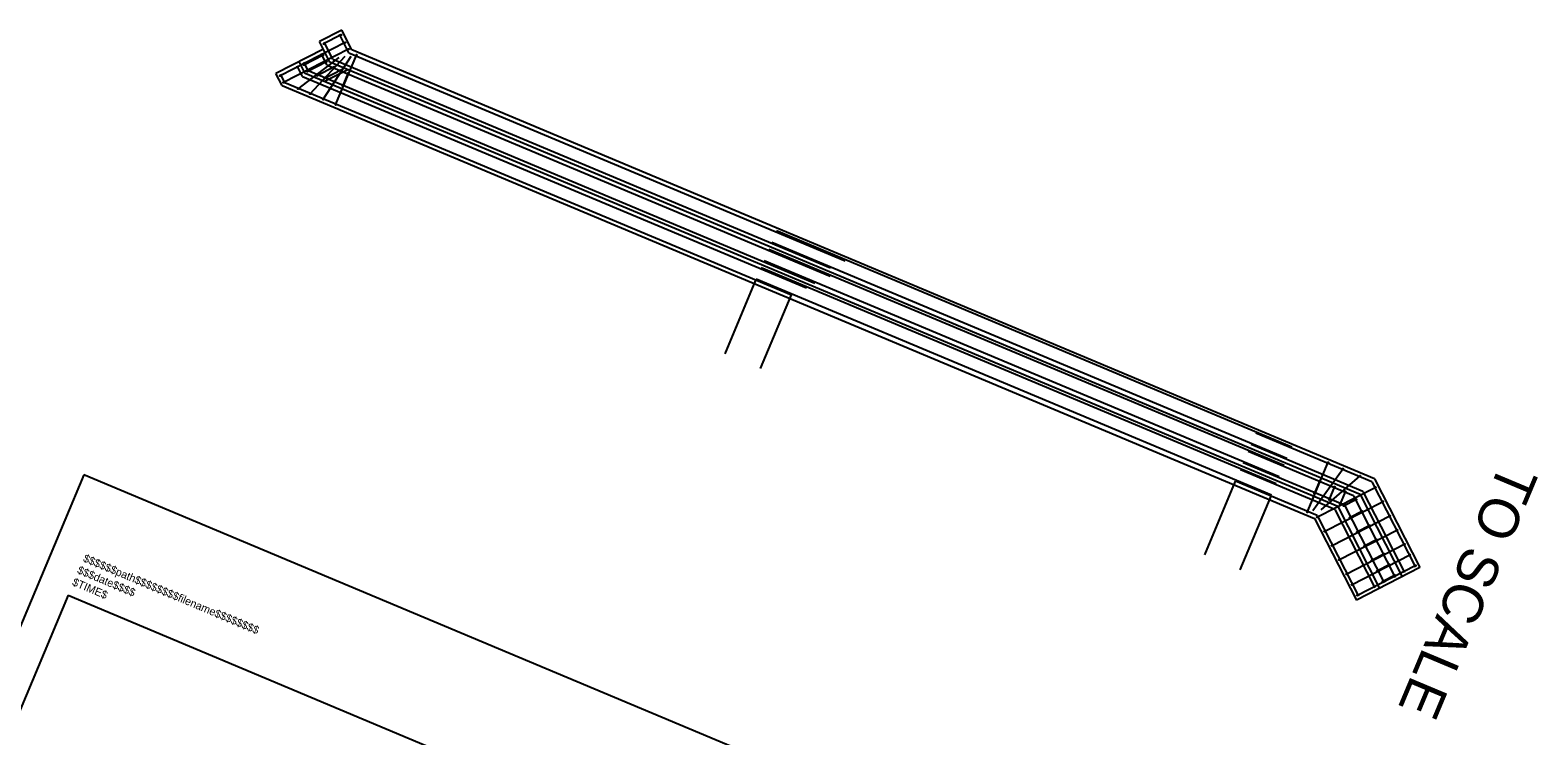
# Model space of a CAD drawing. Extents: x 1968564 to 1968711, y 796599 to 796794.
# Drawn here: x 1968616.2 to 1968710.6, y 796749.4 to 796793.6 of the extents above; entities that cross this region are included whole.
import ezdxf

# ---------------------------------------------------------------- set-up
doc = ezdxf.new("R2010")
doc.units = 0
for name, color, linetype in [('BR_BORDER LINES', 7, 'Continuous'), ('BR_CONCRETE', 7, 'Continuous'), ('BR_REBAR', 7, 'Continuous'), ('Level 31', 7, 'Continuous'), ('RD_SHT_ID', 7, 'Continuous')]:
    doc.layers.add(name, color=color, linetype=linetype)

msp = doc.modelspace()

# ---------------------------------------------------------------- linework, layer by layer
at = {"layer": 'BR_BORDER LINES'}
for q in [(1968566.464, 796634.028), (1968696.012, 796725.723)]:
    msp.add_line((1968618.549, 796758.212), q, dxfattribs=at)
at = {"layer": 'BR_CONCRETE'}
for p, q in [((1968635.689, 796793.605), (1968634.291, 796792.889)), ((1968636.316, 796792.381), (1968635.689, 796793.605)), ((1968634.538, 796792.407), (1968631.57, 796790.887)), ((1968634.952, 796791.597), (1968634.291, 796792.889)), ((1968700.385, 796765.509), (1968636.316, 796792.381)), ((1968633.405, 796790.89), (1968633.026, 796791.632)), ((1968636.067, 796791.13), (1968634.612, 796790.385)), ((1968699.481, 796764.533), (1968634.952, 796791.597)), ((1968631.95, 796790.145), (1968631.57, 796790.887)), ((1968631.95, 796790.145), (1968696.629, 796763.018)), ((1968698.084, 796763.763), (1968633.405, 796790.89)), ((1968700.385, 796765.509), (1968703.236, 796759.941)), ((1968698.084, 796763.763), (1968700.705, 796758.645)), ((1968699.481, 796764.533), (1968702.124, 796759.371)), ((1968696.629, 796763.018), (1968699.25, 796757.9)), ((1968703.236, 796759.941), (1968699.25, 796757.9))]:
    msp.add_line(p, q, dxfattribs=at)
at = {"layer": 'BR_REBAR'}
for p, q in [((1968635.655, 796793.306), (1968634.553, 796792.742)), ((1968636.143, 796792.194), (1968635.552, 796793.347)), ((1968635.902, 796792.824), (1968631.833, 796790.74)), ((1968636.113, 796792.411), (1968632.044, 796790.328)), ((1968633.318, 796791.427), (1968634.534, 796792.049)), ((1968634.779, 796791.41), (1968634.401, 796792.149)), ((1968634.516, 796789.25), (1968636.274, 796791.984)), ((1968635.126, 796791.784), (1968634.58, 796792.85)), ((1968635.305, 796788.919), (1968636.626, 796792.07)), ((1968636.143, 796792.194), (1968667.224, 796779.158)), ((1968633.232, 796790.703), (1968632.888, 796791.375)), ((1968632.938, 796789.915), (1968635.525, 796791.882)), ((1968633.579, 796791.078), (1968633.315, 796791.593)), ((1968633.529, 796791.014), (1968634.745, 796791.637)), ((1968633.579, 796791.078), (1968665.321, 796777.764)), ((1968633.696, 796789.595), (1968635.902, 796791.982)), ((1968635.226, 796791.309), (1968634.144, 796790.754)), ((1968635.68, 796791.119), (1968634.597, 796790.564)), ((1968634.779, 796791.41), (1968666.289, 796778.194)), ((1968635.126, 796791.784), (1968666.298, 796778.71)), ((1968632.124, 796790.332), (1968631.86, 796790.848)), ((1968632.124, 796790.332), (1968663.866, 796777.019)), ((1968633.232, 796790.703), (1968664.813, 796777.458)), ((1968636.099, 796790.935), (1968635.745, 796790.09)), ((1968695.202, 796767.49), (1968662.926, 796781.027)), ((1968694.719, 796766.338), (1968662.442, 796779.875)), ((1968694.904, 796766.779), (1968662.628, 796780.316)), ((1968694.42, 796765.627), (1968662.144, 796779.164)), ((1968659.703, 796773.343), (1968661.637, 796777.954)), ((1968693.937, 796764.474), (1968661.661, 796778.011)), ((1968694.235, 796765.185), (1968661.959, 796778.722)), ((1968661.932, 796772.408), (1968663.866, 796777.019)), ((1968699.654, 796764.72), (1968692.651, 796767.657)), ((1968700.212, 796765.322), (1968692.949, 796768.368)), ((1968698.504, 796763.847), (1968692.168, 796766.504)), ((1968699.061, 796764.449), (1968692.466, 796767.215)), ((1968696.168, 796763.392), (1968697.49, 796766.543)), ((1968697.911, 796763.576), (1968691.983, 796766.062)), ((1968696.517, 796763.516), (1968698.416, 796766.154)), ((1968697.052, 796763.557), (1968699.495, 796765.699)), ((1968689.751, 796760.741), (1968691.684, 796765.352)), ((1968696.802, 796763.205), (1968691.684, 796765.352)), ((1968696.963, 796765.408), (1968696.608, 796764.563)), ((1968696.777, 796763.094), (1968700.467, 796764.983)), ((1968697.885, 796765.021), (1968697.53, 796764.176)), ((1968698.57, 796764.734), (1968698.215, 796763.889)), ((1968699.654, 796764.72), (1968702.261, 796759.629)), ((1968700.212, 796765.322), (1968702.947, 796759.98)), ((1968691.979, 796759.806), (1968693.913, 796764.417)), ((1968697.233, 796762.204), (1968700.923, 796764.093)), ((1968699.261, 796764.219), (1968698.445, 796763.801)), ((1968698.504, 796763.847), (1968700.995, 796758.981)), ((1968699.061, 796764.449), (1968701.681, 796759.332)), ((1968696.802, 796763.205), (1968699.387, 796758.157)), ((1968697.689, 796761.314), (1968701.379, 796763.203)), ((1968697.911, 796763.576), (1968700.416, 796758.684)), ((1968699.64, 796763.479), (1968698.824, 796763.061)), ((1968698.145, 796760.424), (1968701.834, 796762.313)), ((1968700.096, 796762.589), (1968699.28, 796762.171)), ((1968698.601, 796759.533), (1968702.29, 796761.423)), ((1968700.552, 796761.699), (1968699.736, 796761.281)), ((1968698.942, 796758.866), (1968702.632, 796760.755)), ((1968699.284, 796758.198), (1968702.974, 796760.088)), ((1968701.007, 796760.809), (1968700.191, 796760.391)), ((1968701.349, 796760.141), (1968700.533, 796759.723)), ((1968701.691, 796759.473), (1968700.875, 796759.056))]:
    msp.add_line(p, q, dxfattribs=at)
for centre in [(1968635.655, 796793.306), (1968634.534, 796792.049), (1968634.553, 796792.742), (1968635.902, 796792.824), (1968636.113, 796792.411), (1968636.618, 796792.051), (1968633.318, 796791.427), (1968634.745, 796791.637), (1968635.226, 796791.309), (1968635.68, 796791.119), (1968631.833, 796790.74), (1968632.044, 796790.328), (1968633.529, 796791.014), (1968634.144, 796790.754), (1968634.597, 796790.564), (1968635.753, 796790.109), (1968636.091, 796790.916), (1968632.955, 796789.927), (1968633.71, 796789.611), (1968634.527, 796789.268), (1968635.313, 796788.938), (1968697.482, 796766.524), (1968698.404, 796766.137), (1968699.48, 796765.686), (1968696.616, 796764.582), (1968696.955, 796765.389), (1968697.877, 796765.002), (1968698.561, 796764.715), (1968700.449, 796764.974), (1968697.538, 796764.195), (1968698.223, 796763.908), (1968698.464, 796763.811), (1968699.243, 796764.209), (1968700.904, 796764.084), (1968696.176, 796763.411), (1968696.796, 796763.103), (1968698.843, 796763.071), (1968699.621, 796763.469), (1968701.36, 796763.193), (1968697.252, 796762.213), (1968699.298, 796762.18), (1968700.077, 796762.579), (1968701.816, 796762.303), (1968697.708, 796761.323), (1968699.754, 796761.29), (1968700.533, 796761.689), (1968700.989, 796760.799), (1968702.272, 796761.413), (1968698.163, 796760.433), (1968700.21, 796760.4), (1968701.331, 796760.131), (1968702.613, 796760.746), (1968702.955, 796760.078), (1968698.619, 796759.543), (1968700.552, 796759.733), (1968700.894, 796759.065), (1968701.672, 796759.464), (1968698.961, 796758.875), (1968699.303, 796758.208)]:
    msp.add_circle(centre, 0.0208, dxfattribs=at)
at = {"layer": 'Level 31'}
msp.add_lwpolyline([(1968619.541, 796765.748), (1968563.846, 796632.955), (1968644.997, 796598.919), (1968700.693, 796731.712)], close=True, dxfattribs=at)

# ---------------------------------------------------------------- texts
at = {"layer": 'BR_REBAR'}
msp.add_text('TO SCALE', height=2.531, rotation=247.24601, dxfattribs=at).set_placement((1968708.314, 796766.641))
at = {"layer": 'RD_SHT_ID'}
for s, height, p in [('$$$date$$$$', 0.49387, (1968619.079, 796759.611)), ('$$$$$$path$$$$$$$$filename$$$$$$$$', 0.49387, (1968619.446, 796760.35)), ('$TIME$', 0.4939, (1968618.763, 796758.857))]:
    msp.add_text(s, height=height, rotation=337.24601, dxfattribs=at).set_placement(p)

doc.saveas('drawing.dxf')
